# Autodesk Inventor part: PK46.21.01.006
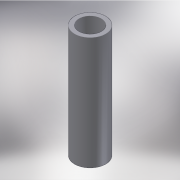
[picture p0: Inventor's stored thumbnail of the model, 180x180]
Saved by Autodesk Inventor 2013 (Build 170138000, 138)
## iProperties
Created: 2005-04
Part Number: PK46.21.01.006
Material: Steel, Mild
Document SubType Name: Modeling
Designer: salex
Manufacturer: Standard
Standards Organization: Custom
Density: 7.86 g/cm^3
Author: salex
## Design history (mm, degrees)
sketch "Эскиз1"
  geometry: C1 r 79.5 at (0, 0); C2 r 109.5 at (0, 0)
  constraints: 2 centre point, 1 coincident, 1 other
  dimensions: "d0" = 219 diameter of C2; "d1" = 159 diameter of C1
extrude "Выдавливание1" new body sketch "Эскиз1" distance "d2" = 800; taper "d3" = 0 deg
body "Solid1"
